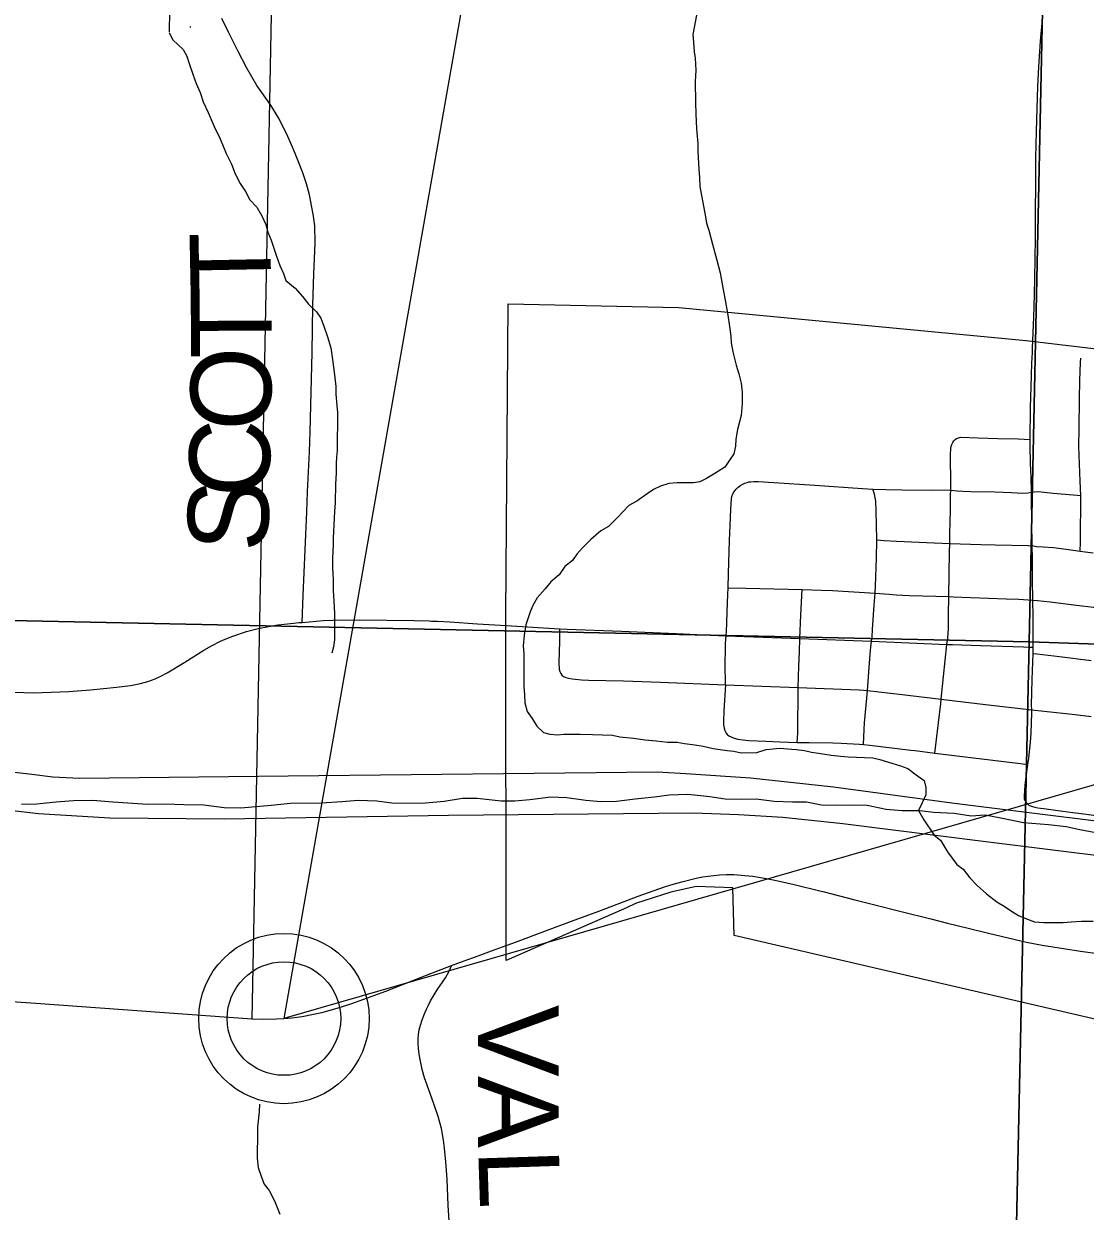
# Model space of a CAD drawing. Extents: x 0 to 34, y 0 to 22.
# Drawn here: x 13.784 to 14.532, y 17.577 to 18.414 of the extents above; entities that cross this region are included whole.
import ezdxf

# ---------------------------------------------------------------- set-up
doc = ezdxf.new("R2010")
doc.units = 0
for name, color, linetype in [('GM_X_City_Street', 7, 'Continuous'), ('GM_X_Corporation', 7, 'Continuous'), ('GM_X_County_Road', 7, 'Continuous'), ('GM_X_Major_River', 7, 'Continuous'), ('GM_X_Minor_River', 7, 'Continuous'), ('GM_X_Rail_Line', 7, 'Continuous'), ('GM_X_State_Route', 7, 'Continuous'), ('GM_X_Township_Road', 7, 'Continuous'), ('GM_X_Township_Road_Text', 7, 'Continuous'), ('SH_Text', 7, 'Continuous')]:
    doc.layers.add(name, color=color, linetype=linetype)

msp = doc.modelspace()

# ---------------------------------------------------------------- linework, layer by layer
at = {"layer": 'GM_X_City_Street'}
msp.add_line((14.49531, 17.97061), (14.4954, 17.97491), dxfattribs=at)
for points in [[(14.52836, 18.04243), (14.5287, 18.04955), (14.52882, 18.08177), (14.52845, 18.09209), (14.5275, 18.11631), (14.5277, 18.1292), (14.52802, 18.14975), (14.52826, 18.16304), (14.5287, 18.17558), (14.5289, 18.17865)], [(14.4261, 17.90032), (14.42689, 17.90802), (14.43023, 17.9353), (14.43056, 17.93831), (14.43222, 17.95428), (14.43457, 17.97692), (14.43525, 17.98127), (14.4357, 17.98808), (14.4358, 17.9978), (14.43602, 18.01065), (14.43637, 18.04222), (14.43652, 18.04815), (14.4367, 18.05585), (14.43686, 18.06279), (14.43703, 18.07157), (14.43713, 18.08225), (14.43734, 18.08555), (14.43745, 18.09049), (14.43737, 18.09632), (14.43719, 18.10392), (14.43708, 18.11061), (14.43727, 18.11517), (14.43765, 18.11647), (14.43806, 18.11784), (14.43863, 18.11914), (14.43953, 18.12049), (14.44042, 18.12144), (14.44142, 18.12216), (14.44264, 18.12258), (14.4442, 18.12292), (14.4567, 18.12254), (14.47038, 18.12212), (14.48481, 18.12177), (14.49329, 18.12142)], [(14.4954, 17.97491), (14.49524, 17.99624), (14.49509, 18.00812), (14.49486, 18.02197), (14.49476, 18.03712), (14.49469, 18.04637), (14.49422, 18.07982), (14.49407, 18.08429), (14.49381, 18.0953), (14.49355, 18.10438), (14.49331, 18.11734), (14.49329, 18.12142)], [(14.27871, 17.94836), (14.27851, 17.95186), (14.27837, 17.95986), (14.27862, 17.97676), (14.27894, 17.98074), (14.27909, 17.98291), (14.2793, 17.98619), (14.27954, 17.992), (14.2799, 18.00006), (14.28032, 18.01212), (14.28048, 18.01672), (14.28071, 18.02699), (14.28116, 18.0423), (14.28153, 18.0501), (14.28178, 18.05558), (14.28216, 18.06629), (14.28237, 18.07226), (14.28275, 18.07952), (14.28306, 18.08122), (14.28378, 18.08314), (14.28494, 18.08494), (14.28608, 18.08635), (14.28761, 18.08772)], [(14.28761, 18.08772), (14.28842, 18.08835), (14.28933, 18.08904), (14.29076, 18.08988), (14.29217, 18.09055), (14.29383, 18.09111), (14.29504, 18.09142), (14.2964, 18.0916), (14.29856, 18.09174), (14.30153, 18.09165), (14.31273, 18.09102), (14.34163, 18.08911), (14.37516, 18.08688), (14.38245, 18.08645)], [(14.37781, 17.93421), (14.37827, 17.93908), (14.37872, 17.94441), (14.37977, 17.96066), (14.38068, 17.9729), (14.38145, 17.97909), (14.38185, 17.98236), (14.3822, 17.98732), (14.38338, 18.00459), (14.38379, 18.01029), (14.38399, 18.013), (14.38417, 18.01797), (14.385, 18.03768), (14.38527, 18.05067), (14.38503, 18.06119), (14.3848, 18.07093), (14.3844, 18.07777), (14.38408, 18.08034), (14.38353, 18.08277), (14.38245, 18.08645)], [(14.38245, 18.08645), (14.39158, 18.08613), (14.40278, 18.08576), (14.42476, 18.08568), (14.43262, 18.08575), (14.43734, 18.08555), (14.44181, 18.08514), (14.44586, 18.08496), (14.45145, 18.08475), (14.46829, 18.08436), (14.47997, 18.08394), (14.48817, 18.08356), (14.49153, 18.08384), (14.49407, 18.08429)], [(14.49407, 18.08429), (14.49616, 18.0845), (14.49877, 18.08463), (14.50942, 18.08358), (14.52641, 18.08209), (14.52882, 18.08177)], [(14.38527, 18.05067), (14.39037, 18.05014), (14.39908, 18.04967), (14.42557, 18.04861), (14.43652, 18.04815), (14.45853, 18.04731), (14.46853, 18.04707), (14.49181, 18.04667), (14.49469, 18.04637)], [(14.53767, 18.04122), (14.53193, 18.04197), (14.52836, 18.04243), (14.51864, 18.04386), (14.50961, 18.04503), (14.50249, 18.0454), (14.49768, 18.04569), (14.49469, 18.04637)], [(14.28048, 18.01672), (14.293, 18.01649), (14.3327, 18.01569), (14.34589, 18.01526), (14.35401, 18.01492), (14.38399, 18.013), (14.39382, 18.01226)], [(14.32918, 17.90788), (14.32952, 17.91437), (14.32986, 17.94647), (14.33036, 17.96161), (14.33078, 17.97174), (14.33089, 17.98109), (14.3317, 17.99757), (14.3327, 18.01569)], [(14.39382, 18.01226), (14.39874, 18.01189), (14.40829, 18.01142), (14.43602, 18.01065), (14.43903, 18.0105), (14.47633, 18.00914), (14.48513, 18.0088), (14.49509, 18.00812)], [(14.49509, 18.00812), (14.49845, 18.00791), (14.50719, 18.00686), (14.52592, 18.0045), (14.53785, 18.00305), (14.54846, 18.00175), (14.56024, 18.00028), (14.56533, 17.99959), (14.59308, 17.99608), (14.60298, 17.99483), (14.61712, 17.99317)], [(14.1618, 17.98785), (14.1617, 17.97912), (14.16116, 17.96385), (14.16149, 17.9594), (14.16191, 17.95779), (14.16255, 17.9563), (14.16344, 17.95522), (14.16459, 17.95437), (14.16626, 17.95364), (14.16814, 17.9531), (14.17056, 17.95264), (14.17717, 17.95198), (14.18203, 17.95176), (14.20677, 17.95127), (14.23289, 17.95029), (14.27871, 17.94836), (14.32986, 17.94647), (14.3728, 17.94481), (14.37613, 17.94461), (14.37872, 17.94441), (14.38046, 17.94423), (14.38486, 17.94373), (14.38661, 17.94351), (14.40314, 17.94153), (14.43056, 17.93831), (14.44021, 17.93717), (14.46171, 17.93463), (14.49432, 17.93086), (14.50297, 17.92989), (14.52497, 17.92744), (14.53623, 17.92618)], [(14.1618, 17.98785), (14.16717, 17.98764), (14.20533, 17.98623), (14.2439, 17.98449), (14.26814, 17.98338), (14.27909, 17.98291), (14.33089, 17.98109), (14.38145, 17.97909), (14.43457, 17.97692), (14.43851, 17.97676), (14.45813, 17.9761), (14.48846, 17.97527), (14.49329, 17.97502), (14.4954, 17.97491)], [(14.49053, 17.86534), (14.48982, 17.86659), (14.4893, 17.8679), (14.48917, 17.8695), (14.48944, 17.87439), (14.49, 17.87974), (14.49163, 17.89229), (14.49222, 17.89682), (14.49335, 17.90802), (14.49389, 17.91445), (14.49419, 17.92219), (14.49428, 17.92793), (14.49432, 17.93086), (14.49414, 17.93416), (14.49461, 17.95208), (14.49531, 17.97061)], [(14.49531, 17.97061), (14.49798, 17.97024), (14.51384, 17.96829), (14.53625, 17.96558)], [(14.27871, 17.94836), (14.27755, 17.93004), (14.27715, 17.92261), (14.27723, 17.92016), (14.27758, 17.91796), (14.2781, 17.91615), (14.27904, 17.91435), (14.28006, 17.91321), (14.2814, 17.91222), (14.28296, 17.91143), (14.28466, 17.91072), (14.28728, 17.91002), (14.29086, 17.90961), (14.29508, 17.90918), (14.30692, 17.9087), (14.31678, 17.90827), (14.32918, 17.90788), (14.33762, 17.9078), (14.35414, 17.90756), (14.36014, 17.90733), (14.37298, 17.90659), (14.37586, 17.90637), (14.38026, 17.90591), (14.40922, 17.90239)], [(14.37586, 17.90637), (14.37625, 17.91692), (14.3766, 17.92157), (14.37781, 17.93421)], [(14.40922, 17.90239), (14.41212, 17.90204), (14.4261, 17.90032), (14.47277, 17.89471), (14.48462, 17.89314), (14.49163, 17.89229)], [(14.49053, 17.86534), (14.49131, 17.86444), (14.49232, 17.86372), (14.49347, 17.86314), (14.49484, 17.86262), (14.49647, 17.86218), (14.49858, 17.86179), (14.5045, 17.86098), (14.51118, 17.86005), (14.51621, 17.85937), (14.52316, 17.85842), (14.52906, 17.85767), (14.53782, 17.85648), (14.54744, 17.85518), (14.57539, 17.85138), (14.59556, 17.84896), (14.60077, 17.84835), (14.61097, 17.84714)]]:
    msp.add_lwpolyline(points, dxfattribs=at)
at = {"layer": 'GM_X_Corporation'}
for points in [[(13.49564, 18.93963), (14.51245, 18.92359), (14.4926, 17.9788), (13.4723, 18.00009)], [(14.51245, 18.92359), (15.51969, 18.90882), (15.50037, 17.94467), (14.4926, 17.9788)], [(14.12416, 17.75411), (14.12384, 17.99777), (14.12545, 18.21705), (14.2457, 18.21434), (14.49034, 18.19103), (14.78118, 18.15667), (14.88115, 18.1407), (14.99378, 18.06821), (15.18555, 18.07245), (15.22414, 18.0733), (15.17106, 17.87356), (15.20251, 17.8656), (15.18408, 17.73958), (14.79859, 17.79075), (14.74846, 17.79396), (14.75535, 17.61323), (14.58889, 17.63142), (14.58748, 17.70162), (14.28481, 17.77174), (14.28379, 17.80545), (14.2579, 17.80636), (14.24004, 17.80235), (14.21513, 17.79424), (14.20893, 17.79132)], [(13.4723, 18.00009), (14.4926, 17.9788), (14.47088, 16.98467), (13.4493, 16.99116)], [(14.4926, 17.9788), (15.50037, 17.94467), (15.48158, 16.92817), (14.47088, 16.98467)]]:
    msp.add_lwpolyline(points, close=True, dxfattribs=at)
at = {"layer": 'GM_X_County_Road'}
for points in [[(14.49578, 18.20756), (14.49629, 18.2234), (14.49659, 18.23477), (14.49703, 18.26312), (14.49722, 18.31989), (14.49771, 18.33862), (14.49808, 18.35441), (14.49865, 18.3702), (14.49944, 18.38411), (14.50057, 18.40204), (14.50184, 18.41741)], [(14.49477, 18.18257), (14.49489, 18.18574), (14.49578, 18.20756)], [(14.49329, 18.12142), (14.49349, 18.14385), (14.49387, 18.1584), (14.49415, 18.16665), (14.49447, 18.17511), (14.49477, 18.18257)], [(13.77787, 17.9433), (13.78438, 17.94302), (13.79121, 17.94287), (13.80964, 17.9434), (13.81615, 17.94379), (13.83135, 17.945), (13.84975, 17.94683), (13.85961, 17.94802), (13.86304, 17.94858), (13.86649, 17.94932), (13.87169, 17.9508), (13.87676, 17.95256), (13.88094, 17.95448), (13.88539, 17.95696), (13.89768, 17.96445), (13.91118, 17.97282), (13.91663, 17.97595), (13.92294, 17.97911), (13.92624, 17.98057), (13.93154, 17.98278), (13.9411, 17.98602), (13.94954, 17.98808), (13.95673, 17.98961), (13.9632, 17.99064), (13.97449, 17.9919), (13.97801, 17.99225), (13.98051, 17.99247), (13.99519, 17.9937), (14.00205, 17.99402), (14.02069, 17.99418), (14.05938, 17.99381), (14.06998, 17.99346), (14.0716, 17.99338)], [(14.0716, 17.99338), (14.07582, 17.99319), (14.08434, 17.99273), (14.104, 17.99151), (14.12415, 17.99014), (14.1618, 17.98785)]]:
    msp.add_lwpolyline(points, dxfattribs=at)
at = {"layer": 'GM_X_Major_River'}
for points in [[(13.80725, 17.86596), (13.81936, 17.86692), (13.833, 17.86715), (13.84705, 17.86586), (13.86109, 17.86496), (13.87171, 17.86438), (13.88384, 17.86458), (13.89711, 17.86404), (13.91114, 17.86389), (13.92557, 17.86186), (13.93732, 17.86167), (13.95852, 17.86354), (13.97214, 17.86491), (13.99374, 17.86527), (14.0085, 17.86627), (14.01986, 17.86722), (14.03313, 17.86668), (14.04529, 17.86499), (14.06727, 17.86535), (14.08051, 17.86633), (14.09337, 17.86844), (14.1036, 17.86861), (14.12068, 17.86662), (14.13016, 17.86678), (14.14075, 17.86771), (14.15551, 17.86948), (14.16689, 17.86891), (14.18018, 17.86723), (14.19081, 17.86627), (14.2018, 17.86645), (14.21503, 17.86819), (14.22866, 17.86955), (14.23887, 17.87086), (14.25212, 17.87146), (14.26769, 17.86982), (14.27833, 17.8681), (14.28971, 17.86792), (14.30032, 17.86809), (14.31285, 17.8664), (14.32575, 17.86586), (14.3356, 17.86602), (14.34625, 17.86392), (14.35686, 17.86372), (14.36633, 17.86388), (14.37846, 17.8637), (14.39178, 17.86089), (14.40317, 17.85994), (14.41567, 17.85977), (14.42517, 17.85878), (14.43959, 17.85789), (14.45174, 17.85619), (14.46159, 17.85674), (14.47261, 17.85464), (14.48859, 17.85149), (14.50605, 17.84989), (14.51858, 17.84858), (14.52809, 17.84646), (14.53949, 17.84437)], [(13.78264, 17.86441), (13.79363, 17.8646), (13.80725, 17.86596)]]:
    msp.add_lwpolyline(points, dxfattribs=at)
at = {"layer": 'GM_X_Minor_River'}
for points in [[(13.88748, 18.45367), (13.88668, 18.40837)], [(14.2592, 18.42535), (14.25571, 18.40672), (14.2561, 18.4014), (14.25651, 18.39457), (14.25728, 18.39001), (14.25769, 18.38166), (14.25734, 18.37369), (14.25739, 18.35888), (14.2578, 18.3509), (14.25822, 18.34027), (14.25901, 18.33002), (14.25903, 18.32432), (14.25983, 18.31179), (14.26023, 18.3061), (14.26064, 18.29964), (14.26451, 18.27839), (14.26528, 18.27383), (14.26682, 18.2689), (14.26951, 18.25903), (14.27259, 18.24764), (14.2749, 18.23891), (14.27683, 18.22829), (14.27838, 18.21956), (14.28032, 18.20893), (14.28148, 18.20096), (14.28227, 18.19412), (14.28266, 18.18957), (14.28382, 18.18311), (14.28613, 18.17362), (14.28805, 18.16755), (14.2896, 18.1611), (14.29038, 18.15464), (14.2904, 18.14667), (14.28967, 18.13832), (14.28705, 18.12844), (14.28593, 18.1216), (14.28557, 18.11666), (14.28445, 18.11135), (14.28143, 18.10678), (14.27803, 18.10184), (14.27121, 18.09727), (14.26515, 18.09384), (14.2606, 18.09156), (14.25605, 18.09079), (14.24466, 18.09076), (14.23859, 18.09038), (14.2329, 18.08846), (14.22797, 18.08618), (14.22342, 18.08313), (14.21623, 18.0778), (14.21055, 18.07475), (14.2026, 18.06639), (14.19617, 18.05992), (14.19087, 18.05687), (14.18367, 18.05078), (14.178, 18.04508), (14.17384, 18.04051), (14.17082, 18.03595), (14.16552, 18.03176), (14.16136, 18.02606), (14.15568, 18.02111), (14.15152, 18.01617), (14.14585, 18.0097), (14.14283, 18.00438), (14.14095, 17.99982), (14.13794, 17.9907), (14.13683, 17.98348), (14.1361, 17.97589), (14.1365, 17.97057), (14.13658, 17.94703), (14.13697, 17.94171), (14.13738, 17.93564), (14.13892, 17.92957), (14.14235, 17.92464), (14.14578, 17.91933), (14.15036, 17.91478), (14.15492, 17.91365), (14.16023, 17.91328), (14.16479, 17.91367), (14.17618, 17.91369), (14.18491, 17.91332), (14.19896, 17.91297), (14.20428, 17.91184), (14.21378, 17.91072), (14.22213, 17.9096), (14.22973, 17.90885), (14.2377, 17.9081), (14.24454, 17.90812), (14.24985, 17.90699), (14.25707, 17.90624), (14.26277, 17.90511), (14.26999, 17.90361), (14.27987, 17.90211), (14.28442, 17.90174), (14.28974, 17.90061), (14.30075, 17.90063), (14.3072, 17.90292), (14.31213, 17.90331), (14.31707, 17.9037), (14.32238, 17.90333), (14.32846, 17.90296)], [(13.88667, 18.40794), (13.88935, 18.40301), (13.89658, 18.39618), (13.89925, 18.39163), (13.90079, 18.38632), (13.90348, 18.37873), (13.90578, 18.37228), (13.90846, 18.36583), (13.91076, 18.35938), (13.9142, 18.35179), (13.91841, 18.34192), (13.92262, 18.3332), (13.92683, 18.32295), (13.93065, 18.31536), (13.93333, 18.30854), (13.93678, 18.30171), (13.94059, 18.29602), (13.94365, 18.29033), (13.9486, 18.28502), (13.95204, 18.27895), (13.95472, 18.27288), (13.95626, 18.26757), (13.95856, 18.26188), (13.96239, 18.25049), (13.96469, 18.24404), (13.96737, 18.23835), (13.96891, 18.23342), (13.97538, 18.22811), (13.98071, 18.22204), (13.98491, 18.21674), (13.99062, 18.21143), (13.99367, 18.20688), (13.99559, 18.20119), (13.99828, 18.1936), (14.00058, 18.18601), (14.00175, 18.17765), (14.00331, 18.16703), (14.0041, 18.15867), (14.00411, 18.15336), (14.0049, 18.14539), (14.0053, 18.14045), (14.00533, 18.13057), (14.00498, 18.12336), (14.00501, 18.11349), (14.00465, 18.10893), (14.00428, 18.10437), (14.00431, 18.09792), (14.00396, 18.08994), (14.00362, 18.07665), (14.00326, 18.07057), (14.00255, 18.05652), (14.00219, 18.05196), (14.00221, 18.04703), (14.00186, 18.03753), (14.00188, 18.03108), (14.00229, 18.02235), (14.00232, 18.01475), (14.00272, 18.00754), (14.00314, 17.99881), (14.00317, 17.98817), (14.0032, 17.9802), (14.00246, 17.97526), (14.00133, 17.9707)], [(13.90149, 18.4117), (13.9021, 18.41258)], [(14.32846, 17.90296), (14.33416, 17.90221), (14.3391, 17.90108), (14.34403, 17.90033), (14.35315, 17.89882), (14.35961, 17.89808), (14.36493, 17.89771), (14.38239, 17.89698), (14.38733, 17.89585), (14.39569, 17.89321), (14.40178, 17.89132), (14.4071, 17.88943), (14.41281, 17.88489), (14.41852, 17.8811), (14.41967, 17.87617), (14.41969, 17.87085), (14.41705, 17.86515), (14.41462, 17.85978)], [(14.41462, 17.85978), (14.41823, 17.85338), (14.42549, 17.84238), (14.43005, 17.83897), (14.43502, 17.83063), (14.4415, 17.82191), (14.44607, 17.8185), (14.45065, 17.81243), (14.4556, 17.80712), (14.46246, 17.80106), (14.46969, 17.79538), (14.47502, 17.79235), (14.47996, 17.78894), (14.48491, 17.78591), (14.48947, 17.78402), (14.49632, 17.78138), (14.50277, 17.78101), (14.51644, 17.78103), (14.52213, 17.78142), (14.52935, 17.78182), (14.5377, 17.78183)], [(13.95043, 17.65278), (13.95007, 17.64746), (13.94897, 17.63683), (13.949, 17.62847), (13.94865, 17.61974), (13.94866, 17.6148), (13.94945, 17.60835), (13.95175, 17.60152), (13.95366, 17.59659), (13.9571, 17.59204), (13.96092, 17.58483), (13.96475, 17.57534)]]:
    msp.add_lwpolyline(points, dxfattribs=at)
at = {"layer": 'GM_X_Rail_Line'}
for points in [[(14.90033, 17.80647), (14.73866, 17.82966), (14.59978, 17.84477), (14.43811, 17.86491), (14.35463, 17.87631), (14.29632, 17.88267), (14.25073, 17.88558), (14.23059, 17.88691), (13.97059, 17.88399), (13.8235, 17.8824), (13.80468, 17.88346), (13.7901, 17.88532), (13.76545, 17.88797)], [(13.74001, 17.86404), (13.79479, 17.85776), (13.8449, 17.85469), (13.92574, 17.85403), (14.08342, 17.85653), (14.25612, 17.85826), (14.28777, 17.85708), (14.31905, 17.85522), (14.36121, 17.85072), (14.46202, 17.838), (14.55254, 17.82673), (14.63073, 17.81732), (14.73449, 17.80474)]]:
    msp.add_lwpolyline(points, dxfattribs=at)
at = {"layer": 'GM_X_State_Route'}
msp.add_line((14.1138, 17.76084), (14.12415, 17.76465), dxfattribs=at)
for points in [[(14.15254, 17.77517), (14.17024, 17.78178), (14.18932, 17.78897), (14.21705, 17.79938), (14.23559, 17.80602), (14.24175, 17.80801), (14.24786, 17.80968), (14.25784, 17.81205), (14.26276, 17.81304), (14.26647, 17.81364), (14.27051, 17.81412), (14.27449, 17.81452), (14.27923, 17.81472), (14.28133, 17.81479)], [(14.28133, 17.81479), (14.28446, 17.81467), (14.29221, 17.81413), (14.29775, 17.81359), (14.30318, 17.81274), (14.30755, 17.81203), (14.31209, 17.81108), (14.31671, 17.81009)], [(14.31671, 17.81009), (14.32709, 17.80762), (14.34608, 17.80294), (14.34706, 17.80269)], [(14.34706, 17.80269), (14.36975, 17.797), (14.37722, 17.7951)], [(14.37722, 17.7951), (14.38189, 17.79392), (14.40236, 17.78861), (14.42323, 17.78346), (14.43503, 17.78049), (14.44945, 17.77703), (14.46381, 17.77344), (14.49075, 17.76717), (14.50163, 17.76494), (14.51659, 17.76251), (14.52875, 17.76062), (14.5563, 17.75685), (14.56513, 17.75565), (14.57193, 17.755), (14.57587, 17.75485), (14.58064, 17.75492), (14.58344, 17.7552), (14.58629, 17.75577), (14.5885, 17.75651), (14.59043, 17.75748), (14.59256, 17.75898), (14.59413, 17.7604)], [(14.12415, 17.76465), (14.12886, 17.76639), (14.15254, 17.77517)], [(14.08572, 17.75059), (14.09442, 17.7538), (14.10439, 17.75737), (14.1138, 17.76084)], [(13.75146, 17.72695), (13.79283, 17.72405), (13.94505, 17.71294), (13.95266, 17.71287), (13.96224, 17.71298), (13.96758, 17.71321), (13.97304, 17.71369), (13.98032, 17.71473), (13.98848, 17.71624), (13.99429, 17.71754), (14.00501, 17.72055), (14.01471, 17.72356), (14.02393, 17.72678), (14.03936, 17.73258), (14.06801, 17.74372), (14.08572, 17.75059)]]:
    msp.add_lwpolyline(points, dxfattribs=at)
at = {"layer": 'GM_X_Township_Road'}
for points in [[(13.98051, 17.99247), (13.98103, 18.01164), (13.98257, 18.04364), (13.98367, 18.07037), (13.98427, 18.08444), (13.98487, 18.09846), (13.98548, 18.11271), (13.98603, 18.12665), (13.98755, 18.18255), (13.98799, 18.21589), (13.98866, 18.23816), (13.98938, 18.25436), (13.9896, 18.2602), (13.98924, 18.27183), (13.98838, 18.27874), (13.98656, 18.28892), (13.98551, 18.29384), (13.98348, 18.30145), (13.98081, 18.30925), (13.97819, 18.31588), (13.9755, 18.32284), (13.97288, 18.32912), (13.97033, 18.33487), (13.96678, 18.34226), (13.96364, 18.34813), (13.95826, 18.35701), (13.94857, 18.37082), (13.94134, 18.38295), (13.93505, 18.3952), (13.92848, 18.40851), (13.92391, 18.41803)], [(14.08425, 17.5671), (14.08332, 17.58153), (14.08246, 17.60006), (14.08166, 17.61217), (14.08075, 17.62177), (14.08001, 17.62747), (14.07867, 17.63571), (14.07622, 17.64427), (14.07347, 17.65229), (14.07047, 17.66042), (14.06668, 17.67149), (14.06503, 17.67742), (14.06381, 17.68329), (14.06289, 17.68823), (14.06246, 17.69204), (14.06223, 17.69562), (14.06212, 17.69869), (14.06235, 17.70189), (14.06294, 17.7052), (14.06377, 17.70859), (14.06487, 17.71226), (14.06648, 17.71664), (14.06801, 17.71994), (14.06936, 17.72276), (14.07086, 17.72569), (14.07271, 17.72887), (14.0756, 17.73345), (14.08128, 17.74197), (14.08395, 17.74671), (14.0849, 17.74868), (14.08572, 17.75059)]]:
    msp.add_lwpolyline(points, dxfattribs=at)
at = {"layer": 'SH_Text'}
for p, q in [((13.97466, 19.27245), (13.94505, 17.71294)), ((14.19137, 18.98652), (13.96758, 17.71321)), ((15.49839, 18.1549), (13.96758, 17.71321))]:
    msp.add_line(p, q, dxfattribs=at)
for radius in [0.06, 0.04]:
    msp.add_circle((13.96758, 17.71321), radius, dxfattribs=at)

# ---------------------------------------------------------------- texts
at = {"layer": 'GM_X_Township_Road_Text'}
for s, rotation, p in [('T', 91.10066, (13.95875, 18.22183)), ('T', 90.30565, (13.95898, 18.17847)), ('O', 89.1047, (13.95819, 18.12718)), ('C', 88.66505, (13.9571, 18.08005)), ('S', 88.66943, (13.95621, 18.04173)), ('V', 270, (14.10425, 17.72288)), ('A', 270.12948, (14.10425, 17.67274)), ('L', 271.88312, (14.1044, 17.62084))]:
    msp.add_text(s, height=0.05682, rotation=rotation, dxfattribs=at).set_placement(p)

doc.saveas('drawing.dxf')
